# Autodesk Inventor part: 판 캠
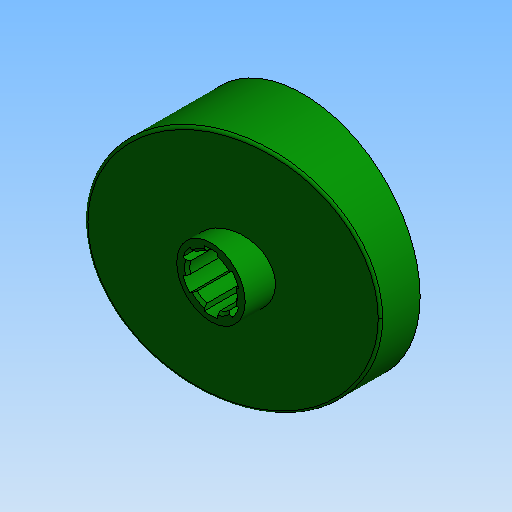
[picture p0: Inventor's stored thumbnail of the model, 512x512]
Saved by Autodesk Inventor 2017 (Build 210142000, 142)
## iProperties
Created: 2021-07
Part Number: 판 캠
Document SubType Name: 모델링
Designer: mdu
Material: 알루미늄 6061
Density: 2.71 g/cm^3
Mass: 235.299 g
Surface Area: 331.301 cm^2
Volume: 86.8262 cm^3
Appearance: 진녹색
변환 표준: STEP AP214IS
파일 이름: C:\Users\SeoGD\Desktop\?쒗뿕\??stp
전처리기: Build: 253, Release: 2010 SP1 - Date: Wed 07/29/2009
전송 단위: 밀리미터
불확실성: 0.01
Author: mdu
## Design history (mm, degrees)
node "작업 평면4"
sketch "스케치1"
  geometry: C1 r 44.5 at (0, 0); 1 further point
  constraints: 1 centre point, 1 coincident
  dimensions: "d25" = 89 diameter of C1
extrude "돌출1" new body sketch "스케치1" distance "d1" = 40; taper "d2" = 0 deg
sketch "스케치2"
  geometry: L1 (-44.5, 15)-(44.5, 38.847); L2 (-44.5, 0)-(-44.5, 40) reference; L3 (-44.5, 40)-(44.5, 40) reference; L4 (44.5, 0)-(44.5, 40) reference; 1 further point
  constraints: 2 end point, 2 point on line
  dimensions: "d26" = 15 distance of L2.start L1.start; "d27" = 75 deg angle of L1 L2
extrude "돌출2" cut sketch "스케치2" stored distance "d5" = 40; taper "d6" = 0 deg
node "작업 평면1"
sketch "스케치3"
  geometry: C1 r 13 at (0, 0); 1 further point
  constraints: 1 centre point, 1 coincident
  dimensions: "d9" = 26 diameter of C1
extrude "돌출3" join sketch "스케치3" distance "d10" = 38; taper "d11" = 0 deg
hole "구멍1" diameter "d14" = 18; stored, may be unused: countersink angle "d18" = 90 deg, drill point angle "d20" = 118 deg; dims "d12" = 10, "d13" = 10, "d15" = 6, "d16" = 4, "d17" = 2, "d19" = 8
feature "쉘2" dims "d29" = 5
sketch "스케치6"
  geometry: C1 r 17.5 at (0, 0); C2 r 14 at (0, 0) reference; 1 further point
  constraints: 1 centre point, 1 coincident
  dimensions: "d28" = 35 diameter of C1
extrude "돌출4" join sketch "스케치6" stored distance "d30" = 38; taper "d31" = 0 deg
fillet "모깎기1" dims "d32" = 3
chamfer "모따기1" distance "d21" = 1; stored, may be unused: second distance "d22" = 2, angle "d23" = 45 deg
sketch "스케치7"
  geometry: L1 (-12.374, 12.374)-(-27.931, 27.931); A1 r 39.5 centre (0, 0) between (-27.931, 27.931) and (0, 39.5) reference; 2 further points
  constraints: 2 end point, 2 point on circle, 1 point on line, 1 vertical alignment, 2 other
  dimensions: "d33" = 45 deg dimension on point (0, 0) L1.start A1.end
feature "리브1" sketch "스케치7" dims "d34" = 5, "d35" = 1, "d36" = 0
fillet "모깎기2" dims "d37" = 3
sketch "스케치8"
  geometry: L1 (2.5, 10.712)-(2.5, 8.646); L2 (-2.5, 10.712)-(-2.5, 8.646); A1 r 11 centre (0, 0) between (2.5, 10.712) and (-2.5, 10.712); A2 r 9 centre (0, 0) between (2.5, 8.646) and (-2.5, 8.646) reference; 1 further point
  constraints: 4 end point, 4 point on circle, 2 parallel, 1 centre point, 1 coincident, 1 vertical
  dimensions: "d41" = 22 diameter of A1; "d42" = 5 distance between parallel lines of L1 L2
extrude "돌출5" cut sketch "스케치8" stored distance "d43" = 38; taper "d44" = 0 deg
fillet "모깎기3" dims "d48" = 1
node "솔리드1"
node "솔리드 본체"
node "곡면 본체"
pattern_circular "원형 패턴1" dims angle "d39" = 360 deg
pattern_circular "원형 패턴2" dims angle "d46" = 360 deg
node "솔리드2"
